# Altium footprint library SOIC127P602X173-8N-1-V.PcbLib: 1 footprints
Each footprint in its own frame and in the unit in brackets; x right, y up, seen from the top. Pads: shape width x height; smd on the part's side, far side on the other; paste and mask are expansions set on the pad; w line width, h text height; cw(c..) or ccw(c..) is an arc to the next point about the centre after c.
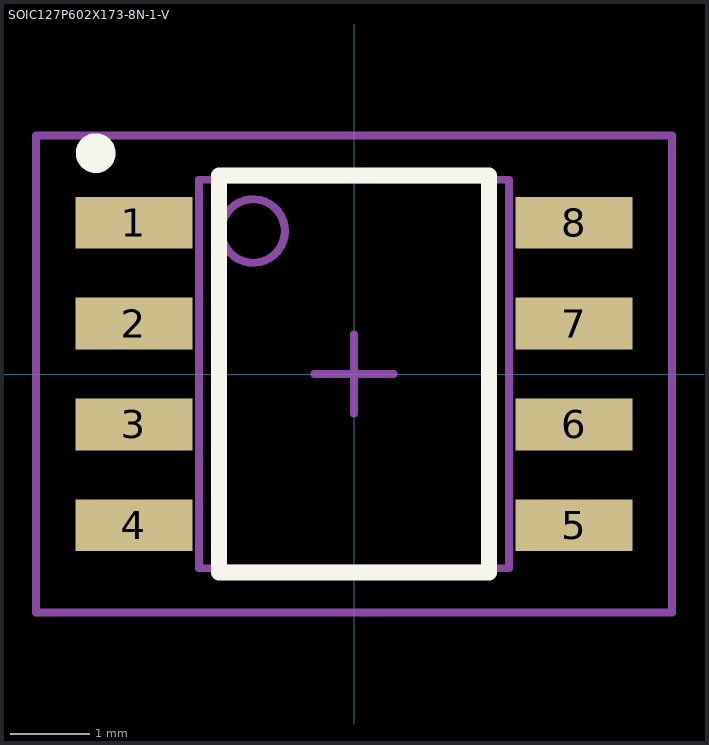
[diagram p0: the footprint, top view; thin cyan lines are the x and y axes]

## SOIC127P602X173-8N-1-V [mm] "SOIC,1.27mm pitch;8 pin,3.899mm W X 4.889mm L X 1.727mm H body"
height 1.727
pads (8):
  rect 1.47x0.65 smd paste+0 mask+0: 1(-2.77,1.905) 2(-2.77,0.635) 3(-2.77,-0.635) 4(-2.77,-1.905) 5(2.77,-1.905) 6(2.77,-0.635) 7(2.77,0.635) 8(2.77,1.905)
Top Overlay:
  circle w0.25: c-3.251,2.78 r0.125
  lines w0.2: -1.7,-2.5 -1.7,2.5 1.7,2.5 1.7,-2.5 -1.7,-2.5
M3 (ASY_Text_Top):
  text ".DESIGNATOR" at -3.643,-0.385 h1.2
M13 (CMP_Body_OTL_Top):
  circle w0.1: c-1.27,1.8 r0.4
  lines w0.1: -1.949,-2.445 -1.949,2.445 1.949,2.445 1.949,-2.445 -1.949,-2.445
M15 (CMP_Courtyard_Top):
  lines w0.1: -0.5,0 0.5,0 ; 0,-0.5 0,0.5 ; -4.005,-3 -4.005,3 4.005,3 4.005,-3 -4.005,-3
3D body "PG-DSO-8-802_51-85066_V0I_3D.stp": height 1.74, standoff 0, extent -3.01,-2.444 3.01,2.445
